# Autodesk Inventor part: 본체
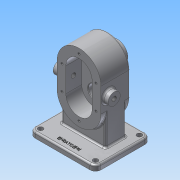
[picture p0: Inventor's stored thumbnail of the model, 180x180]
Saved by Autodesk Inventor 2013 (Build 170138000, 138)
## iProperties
Created: 2020-09
Part Number: 본체
Material: 알루미늄 6061
Document SubType Name: Modeling
Designer: Administrator
Density: 2.71 g/cm^3
Mass: 1445.79 g
Surface Area: 785.637 cm^2
Volume: 533.502 cm^3
Author: Administrator
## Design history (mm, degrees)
sketch "스케치1"
  geometry: L1 (-50, -60)-(50, -60); L2 (50, -60)-(50, 60); L3 (50, 60)-(-50, 60); L4 (-50, 60)-(-50, -60); L5 (-50, -60)-(50, 60); L6 (50, -60)-(-50, 60); 1 further point
  constraints: 12 end point, 2 midpoint, 2 parallel, 1 horizontal, 1 perpendicular
  dimensions: "d0" = 100 distance of L2.end L3.end; "d2" = 120 distance of L1.end L2.end
extrude "돌출1" new body sketch "스케치1" distance "d3" = 10; taper "d4" = 0 deg
node "작업 평면1"
sketch "스케치2"
  geometry: L1 (68, 100)-(112, 100); L2 (112, 20)-(68, 20); L3 (90, 129.148)-(90, -15.718); L4 (0, 0)-(0, 120) reference; A1 r 40 centre (112, 60) between (112, 20) and (112, 100); A2 r 40 centre (68, 60) between (68, 100) and (68, 20); 1 further point
  constraints: 6 end point, 4 point on circle, 3 tangent, 2 centre point, 1 equal radius, 1 horizontal, 1 horizontal alignment, 1 parallel, 1 perpendicular
  dimensions: "d6" = 90 distance between parallel lines of L4 L3; "d7" = 80 distance between parallel lines of L2 L1; "d8" = 22 distance from line of L3 A1.centre; "d9" = 44 distance of A1.centre A2.centre
extrude "돌출2" join sketch "스케치2" distance "d10" = 53; taper "d11" = 0 deg
sketch "스케치3"
  geometry: C1 r 19 at (-112, 60); A1 r 40 centre (-112, 60) between (-112, 100) and (-112, 20) reference; 1 further point
  constraints: 1 centre point, 1 concentric
  dimensions: "d12" = 38 diameter of C1
extrude "돌출3" join sketch "스케치3" distance "d14" = 17; taper "d15" = 0 deg
sketch "스케치4"
  geometry: L1 (68, 100)-(112, 100) reference; L2 (112, 20)-(68, 20) reference; L3 (112, 84)-(68, 84); L4 (68, 36)-(112, 36); A1 r 40 centre (68, 60) between (68, 100) and (68, 20) reference; A2 r 40 centre (112, 60) between (112, 20) and (112, 100) reference; A3 r 24 centre (68, 60) between (68, 84) and (68, 36); A4 r 24 centre (112, 60) between (112, 36) and (112, 84); 1 further point
  constraints: 4 end point, 4 point on circle, 2 centre point, 3 other
  dimensions: "d16" = 24 radius of A4
extrude "돌출4" cut sketch "스케치4" distance "d18" = 29; taper "d19" = 0 deg
hole "구멍1" diameter "d22" = 28; stored, may be unused: countersink angle "d26" = 90 deg, drill point angle "d28" = 0 deg; dims "d20" = 10, "d21" = 10, "d23" = 6, "d24" = 4, "d25" = 2, "d27" = 7.3
hole "구멍2" diameter "d31" = 17; stored, may be unused: countersink angle "d35" = 90 deg, drill point angle "d37" = 0 deg; dims "d29" = 10, "d30" = 10, "d32" = 6, "d33" = 25, "d34" = 15, "d36" = 7.3
hole "구멍3" diameter "d40" = 25; stored, may be unused: countersink angle "d44" = 90 deg, drill point angle "d46" = 0 deg; dims "d38" = 10, "d39" = 10, "d41" = 6, "d42" = 25, "d43" = 15, "d45" = 15
sketch "스케치5"
  geometry: L1 (0, 44)-(0, 0) reference; L2 (-30, -68)-(70, -68) reference; C1 r 11 at (14, 22); 1 further point
  constraints: 1 centre point
  dimensions: "d47" = 14 distance from line of C1.centre L1; "d48" = 90 distance from line of C1.centre L2; "d49" = 22 diameter of C1
extrude "돌출5" join sketch "스케치5" distance "d50" = 10; taper "d51" = 0 deg
hole "구멍4" diameter "d54" = 8.376; stored, may be unused: countersink angle "d58" = 90 deg, drill point angle "d60" = 118 deg; dims "d52" = 10, "d53" = 10, "d55" = 6, "d56" = 25, "d57" = 15, "d59" = 15
node "작업 평면2"
sketch "스케치6"
  geometry: L1 (10, 0)-(10, 120) reference; L2 (68, 100)-(10, 100); L3 (68, 20)-(10, 20); L4 (10, 100)-(10, 20); A1 r 40 centre (68, 60) between (68, 100) and (68, 20) reference; 1 further point
  constraints: 6 end point, 2 point on circle, 2 point on line, 2 tangent, 1 collinear, 1 parallel, 1 perpendicular
extrude "돌출6" join sketch "스케치6" stored distance "d61" = 37; taper "d62" = 0 deg
sketch "스케치7"
  geometry: L1 (68, 84)-(112, 84) reference; L2 (112, 36)-(68, 36) reference; L3 (112, 29)-(68, 29); L4 (68, 91)-(112, 91); A1 r 24 centre (112, 60) between (112, 36) and (112, 84) reference; A2 r 24 centre (68, 60) between (68, 84) and (68, 36) reference; A3 r 31 centre (112, 60) between (112, 29) and (112, 91); A4 r 31 centre (68, 60) between (68, 91) and (68, 29); 7 further points
  constraints: 6 point on circle, 4 coincident, 4 end point, 2 centre point, 3 other
  dimensions: "d63" = 31 radius of A3
hole "구멍5" sketch "스케치7" at (143, 60), (37, 60), (112, 91), (112, 29), (68, 29), (68, 91) diameter "d65" = 4.134; stored, may be unused: countersink angle "d69" = 90 deg, drill point angle "d71" = 118 deg; dims "d66" = 10, "d67" = 25, "d68" = 15, "d70" = 12
chamfer "모따기1" distance "d72" = 0.7; stored, may be unused: second distance "d73" = 2, angle "d74" = 30 deg
chamfer "모따기2" distance "d75" = 1; stored, may be unused: second distance "d76" = 2, angle "d77" = 30 deg
fillet "모깎기1" dims "d78" = 0.5
fillet "모깎기2" dims "d79" = 10
fillet "모깎기3" dims "d80" = 3
fillet "모깎기4" dims "d81" = 3
fillet "모깎기5" dims "d82" = 3
fillet "모깎기6" dims "d83" = 3
fillet "모깎기7" dims "d84" = 3
hole "구멍6" diameter "d87" = 9; stored, may be unused: countersink angle "d91" = 90 deg, drill point angle "d93" = 0 deg; dims "d85" = 10, "d86" = 10, "d88" = 10, "d89" = 25, "d90" = 15, "d92" = 12
hole "구멍7" diameter "d96" = 9; stored, may be unused: countersink angle "d100" = 90 deg, drill point angle "d102" = 0 deg; dims "d94" = 10, "d95" = 10, "d97" = 10, "d98" = 25, "d99" = 15, "d101" = 12
hole "구멍8" diameter "d105" = 9; stored, may be unused: countersink angle "d109" = 90 deg, drill point angle "d111" = 0 deg; dims "d103" = 10, "d104" = 10, "d106" = 10, "d107" = 25, "d108" = 15, "d110" = 12
hole "구멍9" diameter "d114" = 9; stored, may be unused: countersink angle "d118" = 90 deg, drill point angle "d120" = 0 deg; dims "d112" = 10, "d113" = 10, "d115" = 10, "d116" = 25, "d117" = 15, "d119" = 12
sketch "스케치8"
  geometry: L1 (-50, 50)-(-50, -50) reference; L2 (40, 60)-(-40, 60) reference; 2 further points
  constraints: 1 other
  dimensions: "d121" = 12 distance from line of point (-38, 0) L1; "d122" = 60 distance from line of point (-38, 0) L2
feature "엠보싱1" sketch "스케치8" dims "d123" = 0.5, "d124" = 0
fillet "모깎기8" dims "d125" = 3
node "솔리드1"
mirror "대칭1"
mirror "대칭2"
node "투영된 루프1"
